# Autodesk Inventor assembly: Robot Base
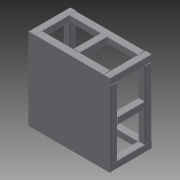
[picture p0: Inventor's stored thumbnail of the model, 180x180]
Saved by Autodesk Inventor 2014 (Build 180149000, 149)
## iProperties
Created: 2008-05
Part Number: Robot Base
Document SubType Name: Assembly
Designer: Jayson Martinez
Author: Jayson Martinez
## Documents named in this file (6)
- C:\Users\iTools\Desktop\tutorial files\Assembly Optimization using FEA\Robot Base.iam
- C:\Users\iTools\Desktop\tutorial files\Assembly Optimization using FEA\corner.ipt
- C:\Users\iTools\Desktop\tutorial files\Assembly Optimization using FEA\Horizontal.ipt
- C:\Users\iTools\Desktop\tutorial files\Assembly Optimization using FEA\base_plate.ipt
- C:\Users\iTools\Desktop\tutorial files\Assembly Optimization using FEA\side.ipt
- C:\Users\iTools\Desktop\tutorial files\Assembly Optimization using FEA\top.ipt
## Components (20 placed, 5 different names)
1. base_plate:1
2. corner:1
3. corner:2
4. corner:3
5. corner:4
6. Horizontal:1
7. Horizontal:2
8. Horizontal:3
9. Horizontal:4
10. Horizontal:5
11. Horizontal:6
12. Horizontal:7
13. Horizontal:8
14. Horizontal:9
15. side:1
16. side:2
17. side:3
18. side:4
19. top:1
20. top:2
## Named parameters: d0_d33 = 0, d1_d34 = 0, d10_d35 = 0, d11_d36 = 0, d17_d29 = 0, d18_d30 = 0, d23_d31 = 0, d24_d32 = 0, d28_d51 = 0, d29_d54 = 0, d34_d50 = 0, d39_d49 = 0, d43_d48 = 0, d46_d52 = 0, d51_d56 = 0, d52_d55 = 0
